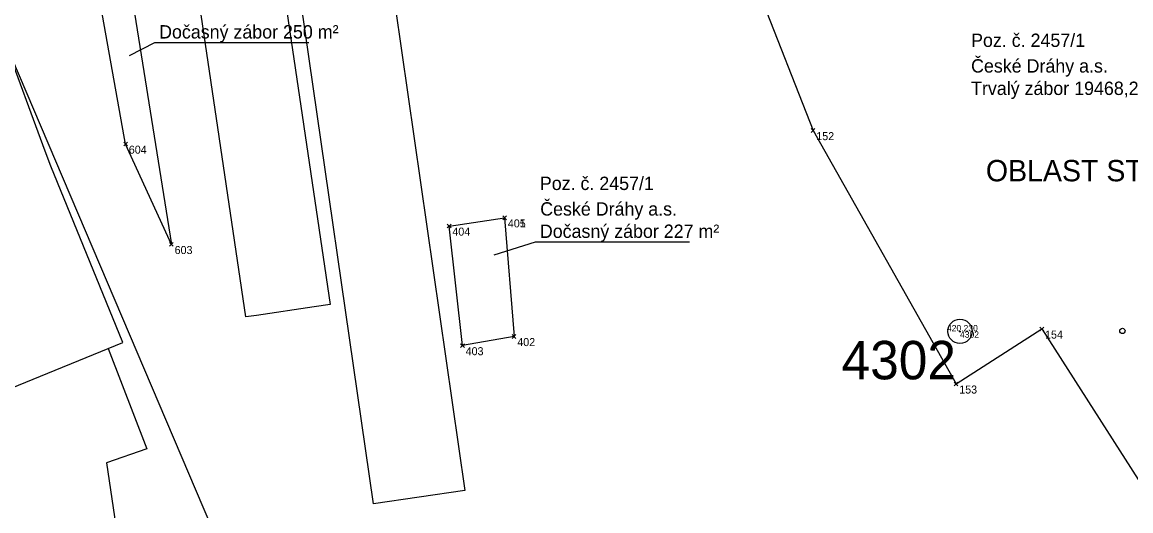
# Model space of a CAD drawing. Extents: x -667048 to -665920, y -1108425 to -1107247.
# Drawn here: x -666746.8 to -666539, y -1107848.7 to -1107757.1 of the extents above; entities that cross this region are included whole.
import ezdxf

# ---------------------------------------------------------------- set-up
doc = ezdxf.new("R2010")
doc.units = 0
for name, color, linetype in [('_JC - Obvod stavby - Přesunutá', 7, 'Continuous'), ('Default', 7, 'Continuous'), ('Hranice parcel', 7, 'Continuous'), ('JC - Popisky', 7, 'Continuous'), ('RK - body obvod stavby trvaly zabor', 7, 'Continuous'), ('RK-body obvod stavby docasny zabor', 7, 'Continuous'), ('RK-hektometry', 7, 'Continuous'), ('Vrstva 1', 7, 'Continuous'), ('Vrstva 60', 7, 'Continuous'), ('Vrstva 61', 7, 'Continuous')]:
    doc.layers.add(name, color=color, linetype=linetype)

# ---------------------------------------------------------------- blocks, each defined once
blk = doc.blocks.new('POINT_DISPLAY')
at = {"layer": 'Default'}
for p, q in [((-354, 354), (354, -354)), ((354, 354), (-354, -354))]:
    blk.add_line(p, q, dxfattribs=at)

msp = doc.modelspace()

# ---------------------------------------------------------------- linework, layer by layer
at = {"layer": '_JC - Obvod stavby - Přesunutá'}
msp.add_lwpolyline([(-666636.61, -1107691.58), (-666636.14, -1107691.33), (-666628.78, -1107705.63), (-666622.68, -1107721.03), (-666608.64, -1107751.77), (-666598.56, -1107777.43), (-666571.77, -1107824.89), (-666555.68, -1107814.6), (-666495.19, -1107909.12)], dxfattribs=at)
for points in [[(-666734.17, -1107742.12), (-666728.02, -1107741.31), (-666718.84, -1107798.76), (-666727.43, -1107779.96)], [(-666656.38, -1107793.77), (-666654.61, -1107816), (-666664.29, -1107817.71), (-666666.78, -1107795.31), (-666656.38, -1107793.77)]]:
    msp.add_lwpolyline(points, close=True, dxfattribs=at)
at = {"layer": 'Hranice parcel'}
for points in [[(-666717.54, -1107626.48), (-666716.29, -1107626.3), (-666689.11, -1107810.01), (-666692.08, -1107810.45), (-666702.89, -1107812.05), (-666704.87, -1107812.34), (-666732.05, -1107628.66)], [(-666699.81, -1107647.09), (-666692.33, -1107646.53), (-666678.06, -1107745.89), (-666663.85, -1107844.88), (-666680.98, -1107847.35), (-666695.25, -1107748.37), (-666709.66, -1107648.37), (-666708.37, -1107648.2)], [(-666730.73, -1107818.25), (-666727.95, -1107817.11), (-666741.44, -1107784.12), (-666742.49, -1107781.31), (-666750.22, -1107760.47)], [(-666705.91, -1107864.42), (-666750.22, -1107760.47)], [(-666761.63, -1107830.87), (-666730.73, -1107818.25)], [(-666730.73, -1107818.25), (-666723.45, -1107837.03), (-666731.03, -1107839.68), (-666729.01, -1107853.18), (-666731.72, -1107876.68), (-666741.76, -1107880.99)]]:
    msp.add_lwpolyline(points, dxfattribs=at)
at = {"layer": 'JC - Popisky'}
for p, q in [((-666721.94, -1107760.92), (-666720.94, -1107760.92)), ((-666650.57, -1107798.27), (-666649.57, -1107798.27))]:
    msp.add_line(p, q, dxfattribs=at)
for points in [[(-666726.67, -1107763.38), (-666721.94, -1107760.92)], [(-666720.94, -1107760.92), (-666693.09, -1107760.92)], [(-666658.33, -1107800.73), (-666650.57, -1107798.27)], [(-666649.57, -1107798.27), (-666621.72, -1107798.27)]]:
    msp.add_lwpolyline(points, dxfattribs=at)
at = {"layer": 'RK-hektometry'}
msp.add_circle((-666540.58, -1107814.96), 0.5, dxfattribs=at)
at = {"layer": 'Vrstva 1'}
msp.add_line((-666571.18, -1107815.04), (-666570.88, -1107815.04), dxfattribs=at)
msp.add_circle((-666571.03, -1107815.04), 2.27, dxfattribs=at)
at = {"layer": 'Vrstva 60'}
msp.add_line((-666571.03, -1107815.04), (-666571.03, -1107815.04), dxfattribs=at)

# ---------------------------------------------------------------- block references
at = {"layer": 'RK - body obvod stavby trvaly zabor', "xscale": 0.0010000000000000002, "yscale": 0.0010000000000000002}
for p in [(-666598.56, -1107777.43), (-666555.68, -1107814.6), (-666571.77, -1107824.89)]:
    msp.add_blockref('POINT_DISPLAY', p, dxfattribs=at)
at = {"layer": 'RK-body obvod stavby docasny zabor', "xscale": 0.0010000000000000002, "yscale": 0.0010000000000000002}
for p in [(-666727.43, -1107779.96), (-666656.38, -1107793.77), (-666656.38, -1107793.77), (-666666.78, -1107795.31), (-666718.84, -1107798.76), (-666664.29, -1107817.71), (-666654.61, -1107816)]:
    msp.add_blockref('POINT_DISPLAY', p, dxfattribs=at)

# ---------------------------------------------------------------- texts
at = {"layer": '_JC - Obvod stavby - Přesunutá'}
msp.add_text('OBLAST STAVBY', height=4, dxfattribs=at).set_placement((-666566.18, -1107786.94))
at = {"layer": 'JC - Popisky'}
for s, p in [('Dočasný zábor 250 m²', (-666721.15, -1107760.19)), ('Poz. č. 2457/1', (-666568.95, -1107761.77)), ('České Dráhy a.s.', (-666568.95, -1107766.57)), ('Trvalý zábor 19468,26 m²', (-666568.95, -1107770.77)), ('Poz. č. 2457/1', (-666649.78, -1107788.57)), ('České Dráhy a.s.', (-666649.71, -1107793.36)), ('Dočasný zábor 227 m²', (-666649.78, -1107797.54))]:
    msp.add_text(s, height=2.5, dxfattribs=at).set_placement(p)
at = {"layer": 'RK - body obvod stavby trvaly zabor'}
for s, p in [('152', (-666597.96, -1107779.23)), ('154', (-666555.08, -1107816.4)), ('153', (-666571.17, -1107826.69))]:
    msp.add_text(s, height=1.5, dxfattribs=at).set_placement(p)
at = {"layer": 'RK-body obvod stavby docasny zabor'}
for s, p in [('604', (-666726.83, -1107781.76)), ('401', (-666655.78, -1107795.57)), ('405', (-666655.78, -1107795.57)), ('404', (-666666.18, -1107797.11)), ('603', (-666718.24, -1107800.56)), ('402', (-666654.01, -1107817.8)), ('403', (-666663.69, -1107819.51))]:
    msp.add_text(s, height=1.5, dxfattribs=at).set_placement(p)
at = {"layer": 'Vrstva 1'}
msp.add_text('4302', height=7.2, dxfattribs=at).set_placement((-666593.21, -1107824.03))
at = {"layer": 'Vrstva 60'}
msp.add_text('4302', height=1.2, dxfattribs=at).set_placement((-666571.03, -1107816.24))
at = {"layer": 'Vrstva 61'}
msp.add_text('420.230', height=1.2, dxfattribs=at).set_placement((-666573.48, -1107815.04))

doc.saveas('drawing.dxf')
